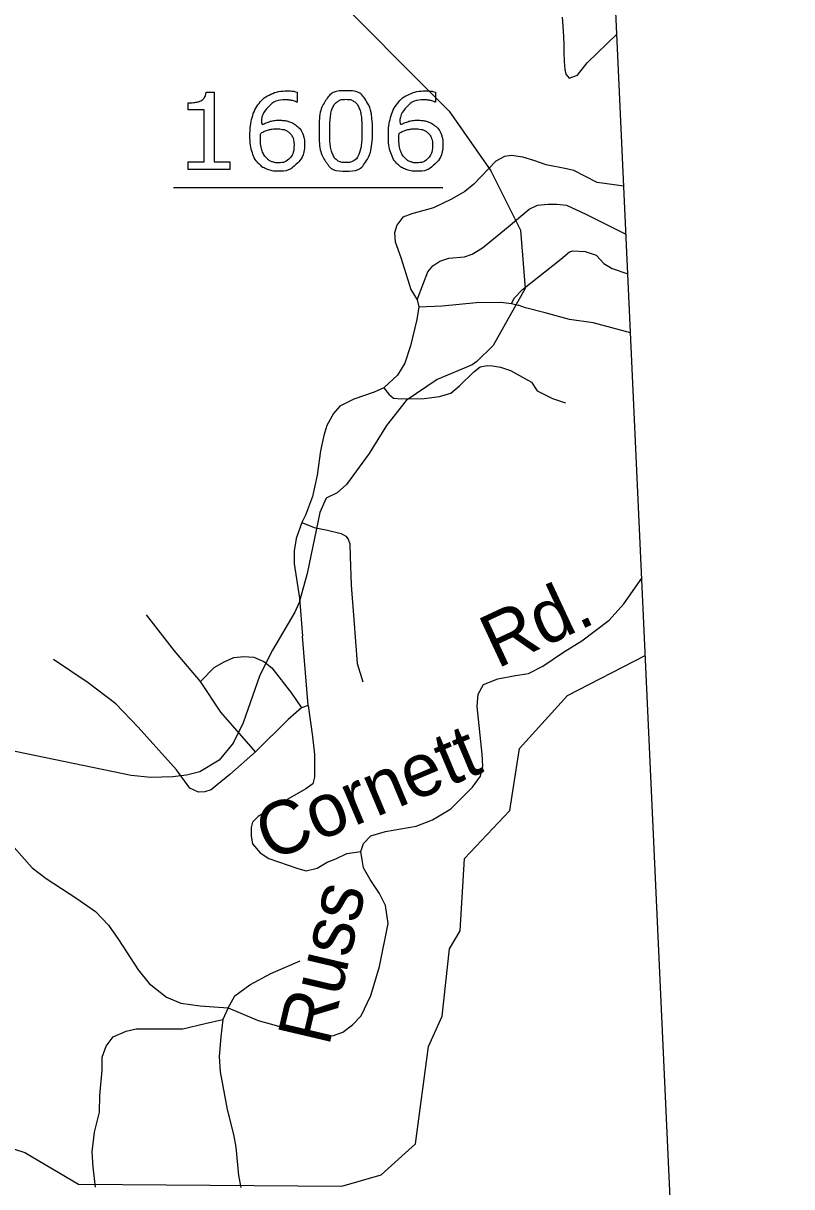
# Model space of a CAD drawing. Extents: x 1190067 to 1192950, y 891516 to 893460.
# Drawn here: x 1191128.6 to 1191171.9, y 893235.3 to 893300.9 of the extents above; entities that cross this region are included whole.
import ezdxf

# ---------------------------------------------------------------- set-up
doc = ezdxf.new("R2010")
doc.units = 0
doc.layers.add('Default', color=7, linetype='Continuous')
doc.layers.add('Prop DSN Text', color=7, linetype='Continuous')

msp = doc.modelspace()

# ---------------------------------------------------------------- linework, layer by layer
at = {"layer": 'Default'}
msp.add_line((1191137.067, 893291.677), (1191152.261, 893291.677), dxfattribs=at)
for points in [[(1191145.357, 893303.28), (1191152.602, 893295.983), (1191154.964, 893292.617), (1191156.627, 893289.277), (1191156.907, 893285.99), (1191155.087, 893282.774), (1191154.178, 893281.865), (1191153.914, 893281.68), (1191151.937, 893280.847), (1191150.187, 893279.67), (1191149.084, 893278.269), (1191148.104, 893276.676), (1191146.827, 893274.927), (1191146.301, 893274.467), (1191145.671, 893274.166), (1191145.322, 893273.349), (1191144.604, 893269.921), (1191144.15, 893268.274), (1191143.904, 893267.743)], [(1191158.98, 893301.282), (1191159.05, 893300.504), (1191159.074, 893299.773), (1191159.074, 893299.301), (1191159.097, 893298.783), (1191159.144, 893298.335), (1191159.192, 893298.075), (1191159.38, 893297.84), (1191159.851, 893298.005), (1191160.393, 893298.712), (1191162.07, 893300.333)], [(1191138.894, 893297.056), (1191139.347, 893297.056), (1191139.347, 893293.136), (1191140.234, 893293.136), (1191140.234, 893292.692)], [(1191144.029, 893297.056), (1191144.029, 893296.495), (1191144, 893296.495)], [(1191151.838, 893297.056), (1191151.838, 893296.495), (1191151.809, 893296.495)], [(1191140.234, 893292.692), (1191137.88, 893292.692), (1191137.88, 893293.136), (1191138.786, 893293.136), (1191138.786, 893296.051), (1191137.88, 893296.051), (1191137.88, 893296.449)], [(1191162.463, 893291.754), (1191160.958, 893291.969), (1191159.639, 893292.63), (1191159.239, 893292.724), (1191158.084, 893292.96), (1191157.378, 893293.195), (1191156.765, 893293.384), (1191156.129, 893293.478), (1191155.728, 893293.431), (1191155.234, 893293.172), (1191154.009, 893291.875), (1191153.49, 893291.451), (1191152.736, 893291.026), (1191151.723, 893290.531), (1191150.498, 893290.201), (1191150.004, 893290.013), (1191149.65, 893289.565), (1191149.532, 893289.117), (1191149.556, 893288.622), (1191149.886, 893287.726), (1191150.451, 893285.934), (1191150.805, 893285.345), (1191150.897, 893284.95)], [(1191150.805, 893285.345), (1191151.154, 893286.291), (1191151.411, 893286.934), (1191151.686, 893287.264), (1191152.09, 893287.521), (1191152.586, 893287.687), (1191153.467, 893287.779), (1191153.908, 893287.926), (1191154.495, 893288.275), (1191155.945, 893289.469), (1191157.12, 893290.461), (1191157.597, 893290.681), (1191158.203, 893290.736), (1191158.68, 893290.736), (1191159.231, 893290.681), (1191160.314, 893290.167), (1191162.586, 893289.055)], [(1191156.129, 893285.133), (1191156.294, 893285.464), (1191156.753, 893285.923), (1191158.901, 893287.632), (1191159.396, 893288.054), (1191159.58, 893288.109), (1191160.278, 893288.073), (1191160.902, 893287.871), (1191161.342, 893287.393), (1191161.801, 893287.117), (1191162.689, 893286.807)], [(1191150.897, 893284.95), (1191150.79, 893284.238), (1191150.425, 893282.751), (1191150.117, 893281.769), (1191149.696, 893281.096), (1191148.933, 893280.394), (1191148.379, 893280.142), (1191147.229, 893279.749), (1191146.444, 893279.356), (1191146.079, 893278.935), (1191145.715, 893278.262), (1191145.547, 893277.701), (1191145.35, 893276.831), (1191145.154, 893275.456), (1191144.902, 893274.249), (1191144.509, 893273.211), (1191144.307, 893272.789), (1191143.976, 893271.893), (1191143.864, 893271.191), (1191143.864, 893270.462), (1191144.173, 893268.526), (1191144.339, 893266.389)], [(1191150.897, 893284.95), (1191152.219, 893285.005), (1191154.128, 893285.188), (1191155.523, 893285.207), (1191156.129, 893285.133), (1191156.5, 893285.038)], [(1191162.841, 893283.485), (1191160.737, 893284.05), (1191159.396, 893284.233), (1191158.02, 893284.619), (1191156.918, 893284.895), (1191156.5, 893285.038)], [(1191148.933, 893280.394), (1191149.208, 893280.027), (1191149.465, 893279.806), (1191149.942, 893279.769), (1191151.209, 893279.788), (1191152.072, 893279.898), (1191152.696, 893280.082), (1191153.192, 893280.504), (1191153.999, 893281.294), (1191154.367, 893281.57), (1191154.752, 893281.643), (1191155.064, 893281.625), (1191155.505, 893281.551), (1191156.074, 893281.368), (1191157.249, 893280.706), (1191157.579, 893280.21), (1191158.442, 893279.788), (1191159.176, 893279.531)], [(1191144.307, 893272.789), (1191144.986, 893272.513), (1191145.739, 893272.366), (1191146.51, 893272.164), (1191146.785, 893272.017), (1191146.914, 893271.852), (1191147.005, 893271.595), (1191147.024, 893270.878), (1191147.079, 893269.262), (1191147.226, 893267.314), (1191147.428, 893264.834), (1191147.74, 893263.806)], [(1191147.701, 893253.777), (1191147.629, 893254.235), (1191147.782, 893254.698), (1191148.188, 893255.131), (1191149.027, 893255.375), (1191150.758, 893255.672), (1191151.678, 893256.024), (1191152.706, 893256.647), (1191153.923, 893257.865), (1191154.383, 893258.488), (1191154.519, 893259.029), (1191154.464, 893259.733), (1191154.194, 893262.414), (1191154.248, 893263.117), (1191154.546, 893263.659), (1191155.357, 893263.984), (1191156.358, 893264.173), (1191157.089, 893264.282), (1191157.9, 893264.688), (1191159.064, 893265.473), (1191160.092, 893266.123), (1191161.634, 893267.287), (1191162.472, 893268.207), (1191163.474, 893269.645)], [(1191143.904, 893267.743), (1191142.645, 893265.6), (1191141.927, 893264.181), (1191140.981, 893261.499), (1191140.422, 893260.345), (1191139.634, 893259.385), (1191138.55, 893258.739), (1191137.797, 893258.549), (1191137.027, 893258.458), (1191135.785, 893258.423), (1191134.664, 893258.531), (1191126.561, 893260.2)], [(1191141.682, 893259.856), (1191139.736, 893262.097), (1191138.579, 893263.824), (1191137.111, 893265.551), (1191135.532, 893267.59)], [(1191144.656, 893262.465), (1191144.339, 893266.389)], [(1191125.633, 893238.257), (1191128.662, 893237.278), (1191131.69, 893235.493), (1191146.563, 893235.369), (1191148.768, 893236.015), (1191150.712, 893237.756), (1191151.446, 893243.256), (1191152.216, 893244.964), (1191152.62, 893248.748), (1191153.231, 893249.77), (1191153.477, 893253.842), (1191156.031, 893256.549), (1191156.575, 893260.044), (1191159.287, 893263.033), (1191163.673, 893265.297)], [(1191144.656, 893262.465), (1191144.288, 893262.336), (1191143.536, 893261.693), (1191141.682, 893259.856), (1191140.231, 893258.589), (1191139.516, 893258.001), (1191139.185, 893257.725), (1191138.818, 893257.615), (1191138.469, 893257.597), (1191137.974, 893257.817), (1191137.221, 893258.846), (1191135.073, 893261.252), (1191133.806, 893262.575), (1191132.246, 893263.751), (1191130.282, 893265.073)], [(1191138.579, 893263.824), (1191139.35, 893264.614), (1191139.919, 893264.945), (1191140.47, 893265.184), (1191141.021, 893265.239), (1191141.59, 893265.202), (1191142.159, 893264.963), (1191142.6, 893264.596), (1191143.719, 893263.163), (1191144.288, 893262.336)], [(1191144.656, 893262.465), (1191144.894, 893260.72), (1191145.004, 893259.709), (1191145.004, 893258.442), (1191144.913, 893258.056), (1191144.527, 893257.78), (1191142.324, 893256.513), (1191141.829, 893256.219), (1191141.516, 893255.888), (1191141.443, 893255.594), (1191141.443, 893255.098), (1191141.516, 893254.676), (1191141.957, 893254.161), (1191142.434, 893253.849), (1191144.068, 893253.28), (1191144.545, 893253.151), (1191145.17, 893253.298), (1191145.72, 893253.647), (1191146.216, 893253.831), (1191146.84, 893254.125), (1191147.629, 893254.235)], [(1191127.492, 893255.131), (1191129.088, 893253.317), (1191129.872, 893252.722), (1191131.604, 893251.585), (1191132.659, 893250.854), (1191133.389, 893250.096), (1191133.958, 893249.283), (1191135.067, 893247.578), (1191135.689, 893246.793), (1191136.663, 893246.035), (1191137.475, 893245.683), (1191138.557, 893245.547), (1191139.341, 893245.493), (1191140.138, 893245.424), (1191141.83, 893244.708), (1191144.482, 893243.977), (1191145.374, 893243.842), (1191146.078, 893243.869), (1191146.619, 893244.058), (1191147.16, 893244.464), (1191147.647, 893244.979), (1191148.188, 893246.116), (1191148.675, 893247.767), (1191149.162, 893250.177), (1191149.027, 893251.205), (1191148.675, 893251.882), (1191148.161, 893252.667), (1191147.782, 893253.317), (1191147.701, 893253.777)], [(1191140.138, 893245.424), (1191140.524, 893246.108), (1191141.356, 893246.732), (1191142.543, 893247.356), (1191144.206, 893248.069)], [(1191140.138, 893245.424), (1191139.841, 893244.77), (1191139.722, 893243.79), (1191139.633, 893242.69), (1191139.693, 893241.828), (1191140.079, 893239.689), (1191140.435, 893238.292), (1191140.583, 893237.579), (1191140.732, 893235.974), (1191140.851, 893235.291)], [(1191132.659, 893235.314), (1191132.524, 893236.451), (1191132.47, 893237.317), (1191132.605, 893238.427), (1191132.875, 893239.537), (1191132.903, 893240.485), (1191133.038, 893241.92), (1191133.038, 893242.651), (1191133.254, 893243.273), (1191133.66, 893243.788), (1191134.39, 893244.112), (1191134.959, 893244.248), (1191136.311, 893244.248), (1191137.583, 893244.248), (1191138.854, 893244.546), (1191139.841, 893244.77)]]:
    msp.add_lwpolyline(points, dxfattribs=at)
for points in [[(1191137.88, 893296.449), (1191138.064, 893296.449), (1191138.274, 893296.479), (1191138.485, 893296.51), (1191138.593, 893296.568), (1191138.727, 893296.641), (1191138.805, 893296.754), (1191138.882, 893296.866), (1191138.894, 893297.056)], [(1191144.452, 893294.101), (1191144.452, 893293.438), (1191144.015, 893293.019), (1191143.578, 893292.599), (1191142.944, 893292.599), (1191142.623, 893292.599), (1191142.36, 893292.699), (1191142.097, 893292.798), (1191141.896, 893292.994), (1191141.644, 893293.237), (1191141.509, 893293.637), (1191141.373, 893294.037), (1191141.373, 893294.601), (1191141.373, 893295.18), (1191141.497, 893295.627), (1191141.621, 893296.074), (1191141.893, 893296.422), (1191142.15, 893296.752), (1191142.556, 893296.938), (1191142.962, 893297.123), (1191143.503, 893297.123), (1191143.675, 893297.123), (1191143.792, 893297.109), (1191143.909, 893297.094), (1191144.029, 893297.056)], [(1191148.285, 893294.87), (1191148.285, 893293.697), (1191147.919, 893293.148), (1191147.552, 893292.599), (1191146.781, 893292.599), (1191145.999, 893292.599), (1191145.638, 893293.155), (1191145.277, 893293.711), (1191145.277, 893294.864), (1191145.277, 893296.025), (1191145.642, 893296.58), (1191146.007, 893297.134), (1191146.781, 893297.134), (1191147.564, 893297.134), (1191147.925, 893296.571), (1191148.285, 893296.008), (1191148.285, 893294.87)], [(1191152.261, 893294.101), (1191152.261, 893293.438), (1191151.824, 893293.019), (1191151.387, 893292.599), (1191150.754, 893292.599), (1191150.432, 893292.599), (1191150.169, 893292.699), (1191149.907, 893292.798), (1191149.705, 893292.994), (1191149.454, 893293.237), (1191149.318, 893293.637), (1191149.182, 893294.037), (1191149.182, 893294.601), (1191149.182, 893295.18), (1191149.306, 893295.627), (1191149.43, 893296.074), (1191149.702, 893296.422), (1191149.959, 893296.752), (1191150.366, 893296.938), (1191150.772, 893297.123), (1191151.312, 893297.123), (1191151.485, 893297.123), (1191151.602, 893297.109), (1191151.718, 893297.094), (1191151.838, 893297.056)], [(1191144, 893296.495), (1191143.918, 893296.539), (1191143.753, 893296.579), (1191143.588, 893296.619), (1191143.416, 893296.619), (1191142.789, 893296.619), (1191142.415, 893296.226), (1191142.042, 893295.834), (1191141.98, 893295.165), (1191142.225, 893295.314), (1191142.463, 893295.391), (1191142.701, 893295.469), (1191143.013, 893295.469), (1191143.29, 893295.469), (1191143.502, 893295.418), (1191143.713, 893295.366), (1191143.935, 893295.212), (1191144.192, 893295.033), (1191144.322, 893294.762), (1191144.452, 893294.49), (1191144.452, 893294.101)], [(1191147.517, 893293.542), (1191147.619, 893293.779), (1191147.656, 893294.099), (1191147.692, 893294.419), (1191147.692, 893294.87), (1191147.692, 893295.314), (1191147.656, 893295.642), (1191147.619, 893295.97), (1191147.514, 893296.198), (1191147.412, 893296.423), (1191147.235, 893296.537), (1191147.059, 893296.651), (1191146.781, 893296.651), (1191146.507, 893296.651), (1191146.327, 893296.537), (1191146.148, 893296.423), (1191146.043, 893296.192), (1191145.943, 893295.975), (1191145.907, 893295.627), (1191145.87, 893295.279), (1191145.87, 893294.864), (1191145.87, 893294.408), (1191145.903, 893294.1), (1191145.935, 893293.793), (1191146.04, 893293.55), (1191146.136, 893293.322), (1191146.313, 893293.202), (1191146.489, 893293.082), (1191146.781, 893293.082), (1191147.056, 893293.082), (1191147.237, 893293.196), (1191147.418, 893293.311), (1191147.517, 893293.542)], [(1191151.809, 893296.495), (1191151.727, 893296.539), (1191151.562, 893296.579), (1191151.398, 893296.619), (1191151.225, 893296.619), (1191150.598, 893296.619), (1191150.225, 893296.226), (1191149.851, 893295.834), (1191149.79, 893295.165), (1191150.035, 893295.314), (1191150.273, 893295.391), (1191150.51, 893295.469), (1191150.823, 893295.469), (1191151.1, 893295.469), (1191151.311, 893295.418), (1191151.523, 893295.366), (1191151.744, 893295.212), (1191152.001, 893295.033), (1191152.131, 893294.762), (1191152.261, 893294.49), (1191152.261, 893294.101)], [(1191143.859, 893294.076), (1191143.859, 893294.347), (1191143.778, 893294.525), (1191143.698, 893294.703), (1191143.514, 893294.834), (1191143.38, 893294.927), (1191143.217, 893294.957), (1191143.054, 893294.986), (1191142.876, 893294.986), (1191142.628, 893294.986), (1191142.415, 893294.927), (1191142.202, 893294.869), (1191141.977, 893294.747), (1191141.972, 893294.682), (1191141.969, 893294.623), (1191141.966, 893294.563), (1191141.966, 893294.472), (1191141.966, 893294.012), (1191142.061, 893293.745), (1191142.155, 893293.478), (1191142.322, 893293.323), (1191142.456, 893293.195), (1191142.612, 893293.135), (1191142.768, 893293.075), (1191142.952, 893293.075), (1191143.374, 893293.075), (1191143.616, 893293.333), (1191143.859, 893293.592), (1191143.859, 893294.076)], [(1191151.668, 893294.076), (1191151.668, 893294.347), (1191151.588, 893294.525), (1191151.507, 893294.703), (1191151.324, 893294.834), (1191151.19, 893294.927), (1191151.026, 893294.957), (1191150.863, 893294.986), (1191150.685, 893294.986), (1191150.437, 893294.986), (1191150.224, 893294.927), (1191150.011, 893294.869), (1191149.787, 893294.747), (1191149.781, 893294.682), (1191149.778, 893294.623), (1191149.775, 893294.563), (1191149.775, 893294.472), (1191149.775, 893294.012), (1191149.87, 893293.745), (1191149.965, 893293.478), (1191150.131, 893293.323), (1191150.265, 893293.195), (1191150.421, 893293.135), (1191150.577, 893293.075), (1191150.761, 893293.075), (1191151.184, 893293.075), (1191151.426, 893293.333), (1191151.668, 893293.592), (1191151.668, 893294.076)]]:
    msp.add_open_spline(points, degree=3, dxfattribs=at)
at = {"layer": 'Prop DSN Text'}
msp.add_line((1191171.937, 893084.661), (1191159.03, 893366.781), dxfattribs=at)
msp.add_line((1191171.937, 893084.661), (1191159.03, 893366.781), dxfattribs=at)
msp.add_line((1191171.937, 893084.661), (1191159.03, 893366.781), dxfattribs=at)

# ---------------------------------------------------------------- texts
at = {"layer": 'Default'}
for s, rotation, p in [('Rd.', 24.99779, (1191155.31, 893264.531)), ('Cornett', 22.79894, (1191142.503, 893253.66)), ('Russ', 76.76926, (1191145.825, 893243.199))]:
    msp.add_text(s, height=3, rotation=rotation, dxfattribs=at).set_placement(p)

doc.saveas('drawing.dxf')
